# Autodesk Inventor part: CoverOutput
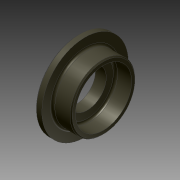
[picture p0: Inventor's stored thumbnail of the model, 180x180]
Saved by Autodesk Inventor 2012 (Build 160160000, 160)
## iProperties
Part Number: CoverOutput
Document SubType Name: Modeling
Created: 2003-11
Designer: ales
Manufacturer: Standard
Standards Organization: Custom
Density: 1 g/cm^3
Material: Default
Control State: 0
Master: False
Checked Out: False
Shininess: 64.0
Length Units: 11269
Angle Units: 11279
Time Units: 11290
Mass Units: 11283
Length Display Precision: 3
Angle Display Precision: 2
Compacted: True
Density: 0.0
Volumn: 0.0
Area: 0.0
PropertySet Name: Model Information
Author: ales
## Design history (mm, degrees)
sketch "Sketch1"
  geometry: L1 (0, 0)-(23.086, 0); L2 (0, 22.5)-(0, 17.5); L3 (2, 22.5)-(2, 40); L4 (2, 40)-(8, 40); L5 (8, 40)-(8, 30); L6 (8, 30)-(25, 30); L7 (0, 22.5)-(2, 22.5); L8 (0, 17.5)-(10, 17.5); L9 (10, 17.5)-(10, 26); L10 (10, 26)-(25, 26); L11 (25, 30)-(25, 26)
  constraints: 22 end point, 6 perpendicular, 1 horizontal, 1 parallel, 1 point on line, 1 vertical, 1 other
  dimensions: "d0" = 35 diameter of L8 L1; "d1" = 52 diameter of L10 L1; "d2" = 15 distance of L9.end L10.end; "d3" = 6 distance of L3.end L4.end; "d4" = 80 diameter of L4 L1; "d5" = 60 diameter of L6 L1; "d6" = 45 diameter of L7 L1; "d7" = 25 distance between parallel lines of L11 L2; "d8" = 8 distance between parallel lines of L2 L5
revolve "Revolution1" sketch "Sketch1" stored, may be unused: angle "d9" = 90 deg
fillet "Fillet1" dims "d10" = 2
chamfer "Chamfer1" distance "d11" = 1; stored, may be unused: second distance "d12" = 2, angle "d31" = 45 deg
body "Solid1"
